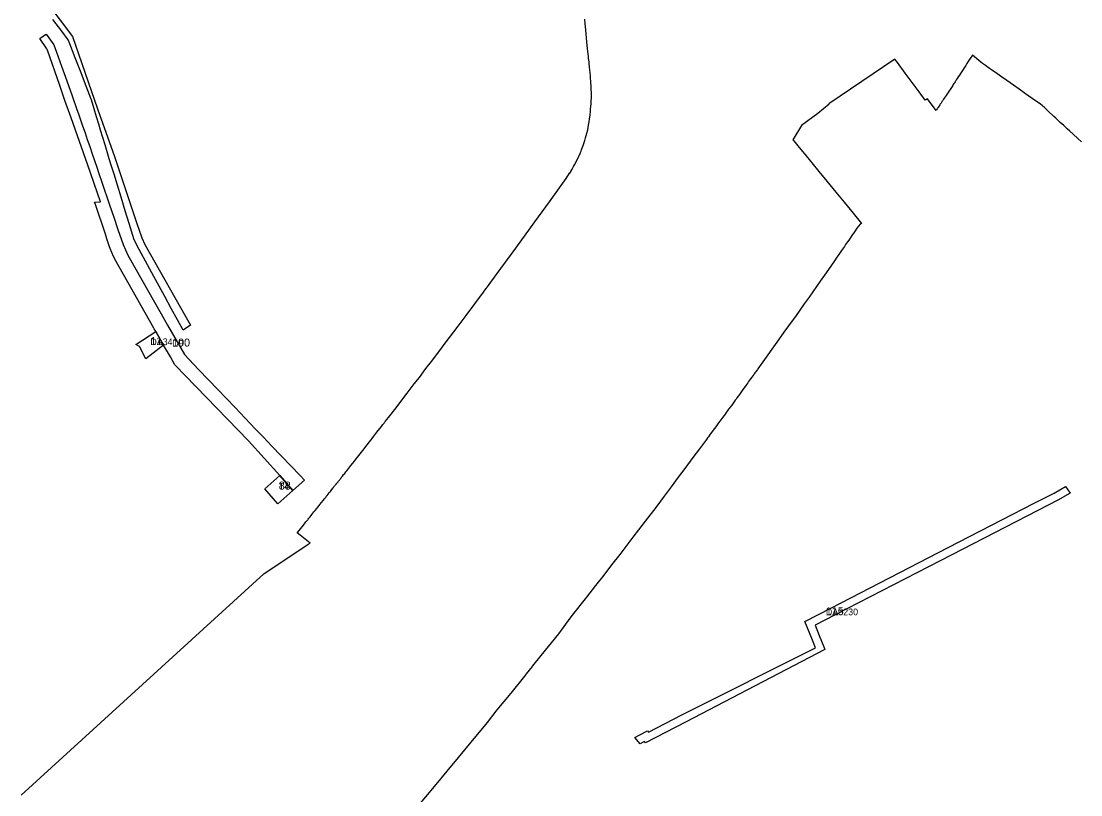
# Model space of a CAD drawing. Extents: x -537012 to -534603, y -1176562 to -1172739.
# Drawn here: x -536874 to -536080, y -1175140 to -1174561 of the extents above; entities that cross this region are included whole.
import ezdxf

# ---------------------------------------------------------------- set-up
doc = ezdxf.new("R2010")
doc.units = 0
for name, color, linetype in [('96120023', 7, 'Continuous'), ('96140023', 7, 'Continuous'), ('ID_VPO', 7, 'Continuous'), ('ID_VPS', 7, 'Continuous')]:
    doc.layers.add(name, color=color, linetype=linetype)

msp = doc.modelspace()

# ---------------------------------------------------------------- linework, layer by layer
at = {"layer": '96120023'}
for points in [[(-536873.93, -1175140.73), (-536692.18, -1174974.82), (-536658.72, -1174952.6), (-536657.33, -1174951.7), (-536664.85, -1174945.87), (-536667.13, -1174944.05), (-536663.21, -1174939.22), (-536661.92, -1174937.56), (-536661.13, -1174936.6), (-536660.5, -1174935.81), (-536660.09, -1174935.3), (-536659.66, -1174934.77), (-536659.18, -1174934.18), (-536658.84, -1174933.75), (-536658.33, -1174933.11), (-536657.79, -1174932.45), (-536657.46, -1174932.04), (-536656.02, -1174930.25), (-536654.54, -1174928.39), (-536653.63, -1174927.29), (-536652.46, -1174925.78), (-536651.59, -1174924.68), (-536650.69, -1174923.6), (-536649.1, -1174921.6), (-536647.46, -1174919.54), (-536647.36, -1174919.42), (-536646.89, -1174918.83), (-536646.5, -1174918.35), (-536646.16, -1174917.92), (-536645.95, -1174917.66), (-536645.77, -1174917.42), (-536645.6, -1174917.21), (-536645.28, -1174916.82), (-536645.18, -1174916.69), (-536645.08, -1174916.56), (-536645, -1174916.46), (-536644.93, -1174916.38), (-536644.87, -1174916.3), (-536644.8, -1174916.21), (-536644.72, -1174916.11), (-536644.65, -1174916.03), (-536644.56, -1174915.91), (-536644.47, -1174915.8), (-536644.39, -1174915.7), (-536644.3, -1174915.59), (-536644.25, -1174915.52), (-536644.21, -1174915.47), (-536644.15, -1174915.4), (-536644.09, -1174915.33), (-536644.07, -1174915.29), (-536642.86, -1174913.78), (-536642.19, -1174912.94), (-536641.63, -1174912.24), (-536641.59, -1174912.18), (-536640.3, -1174910.57), (-536639.98, -1174910.16), (-536639.78, -1174909.91), (-536639.26, -1174909.25), (-536638.99, -1174908.91), (-536638.53, -1174908.33), (-536638.16, -1174907.86), (-536637.78, -1174907.39), (-536637.74, -1174907.34), (-536637.68, -1174907.27), (-536637.64, -1174907.22), (-536637.61, -1174907.17), (-536637.58, -1174907.13), (-536637.54, -1174907.09), (-536637.46, -1174906.99), (-536637.44, -1174906.96), (-536637.41, -1174906.92), (-536637.38, -1174906.89), (-536637.36, -1174906.86), (-536637.33, -1174906.82), (-536637.3, -1174906.79), (-536637.28, -1174906.75), (-536637.26, -1174906.73), (-536637.16, -1174906.61), (-536637.08, -1174906.5), (-536636.98, -1174906.38), (-536636.87, -1174906.25), (-536636.61, -1174905.91), (-536636.43, -1174905.68), (-536636.22, -1174905.42), (-536636.05, -1174905.2), (-536635.67, -1174904.73), (-536635.46, -1174904.47), (-536635.19, -1174904.12), (-536634.89, -1174903.74), (-536634.7, -1174903.51), (-536634.45, -1174903.19), (-536634.25, -1174902.94), (-536633.94, -1174902.54), (-536633.76, -1174902.32), (-536633.61, -1174902.14), (-536633.5, -1174901.99), (-536633.36, -1174901.81), (-536633.19, -1174901.6), (-536632.24, -1174900.39), (-536631.48, -1174899.43), (-536630.64, -1174898.39), (-536629.96, -1174897.51), (-536626.77, -1174893.47), (-536625.41, -1174891.77), (-536624.22, -1174890.21), (-536622.94, -1174888.63), (-536621.83, -1174887.2), (-536620.94, -1174886.06), (-536617.99, -1174882.2), (-536614.51, -1174877.99), (-536612.89, -1174875.89), (-536610.91, -1174873.26), (-536609.59, -1174871.58), (-536608.06, -1174869.62), (-536606.38, -1174867.43), (-536604.86, -1174865.53), (-536603.85, -1174864.22), (-536602.78, -1174862.8), (-536602.25, -1174862.13), (-536601.9, -1174861.7), (-536601.62, -1174861.35), (-536601.37, -1174861.02), (-536601.09, -1174860.66), (-536598.59, -1174857.48), (-536593, -1174850.36), (-536588.63, -1174844.54), (-536584.67, -1174839.44), (-536579.41, -1174832.4), (-536575.45, -1174827.55), (-536570.59, -1174820.91), (-536566.46, -1174815.57), (-536560.15, -1174807.24), (-536556.11, -1174801.9), (-536546.4, -1174789.03), (-536540.49, -1174781.02), (-536527.39, -1174763.63), (-536525.68, -1174761.21), (-536525.56, -1174761.05), (-536525.44, -1174760.88), (-536525.37, -1174760.79), (-536525.32, -1174760.72), (-536525.29, -1174760.69), (-536525.22, -1174760.59), (-536525.2, -1174760.56), (-536525.17, -1174760.53), (-536525.14, -1174760.49), (-536525.12, -1174760.45), (-536525.1, -1174760.43), (-536525.09, -1174760.41), (-536525.06, -1174760.38), (-536525.03, -1174760.34), (-536524.99, -1174760.27), (-536524.96, -1174760.24), (-536524.95, -1174760.23), (-536524.93, -1174760.2), (-536524.9, -1174760.17), (-536524.89, -1174760.15), (-536524.88, -1174760.14), (-536524.87, -1174760.12), (-536524.87, -1174760.11), (-536524.86, -1174760.11), (-536524.86, -1174760.1), (-536524.85, -1174760.09), (-536524.84, -1174760.08), (-536524.83, -1174760.07), (-536524.83, -1174760.06), (-536524.82, -1174760.06), (-536524.82, -1174760.05), (-536524.81, -1174760.04), (-536524.78, -1174760), (-536524.74, -1174759.94), (-536524.56, -1174759.7), (-536524.44, -1174759.54), (-536523.15, -1174757.8), (-536521.87, -1174756.07), (-536514.37, -1174745.87), (-536503.23, -1174730.7), (-536489.05, -1174710.98), (-536478.01, -1174695.81), (-536471.74, -1174687.11), (-536465.57, -1174678.46), (-536464.62, -1174677.1), (-536464.52, -1174676.95), (-536464.35, -1174676.7), (-536463.75, -1174675.8), (-536463.63, -1174675.62), (-536463.59, -1174675.57), (-536463.51, -1174675.44), (-536463.5, -1174675.42), (-536463.47, -1174675.39), (-536463.37, -1174675.23), (-536462.9, -1174674.51), (-536462.79, -1174674.34), (-536461.84, -1174672.83), (-536461.7, -1174672.59), (-536461.07, -1174671.55), (-536459.91, -1174669.56), (-536459.2, -1174668.27), (-536457.41, -1174664.84), (-536455.91, -1174661.68), (-536455.65, -1174661.05), (-536455.33, -1174660.34), (-536455.01, -1174659.61), (-536454.7, -1174658.86), (-536454.33, -1174657.95), (-536454.16, -1174657.54), (-536453.91, -1174656.9), (-536453.67, -1174656.3), (-536452.72, -1174653.7), (-536452.21, -1174652.22), (-536451.93, -1174651.39), (-536451.52, -1174650.08), (-536450.88, -1174647.95), (-536449.92, -1174644.38), (-536449.34, -1174641.85), (-536448.99, -1174640.13), (-536448.64, -1174638.38), (-536448.26, -1174636.09), (-536447.97, -1174634.02), (-536447.54, -1174630.65), (-536447.32, -1174628.16), (-536447.22, -1174626.58), (-536447.15, -1174625.52), (-536447.07, -1174624.96), (-536447.04, -1174624.72), (-536446.99, -1174624.33), (-536446.98, -1174624.28), (-536446.98, -1174624.26), (-536446.98, -1174624.21), (-536446.97, -1174624.17), (-536446.97, -1174624.14), (-536446.96, -1174624.12), (-536446.96, -1174624.11), (-536446.96, -1174624.08), (-536446.96, -1174624.07), (-536446.96, -1174624.06), (-536446.96, -1174624.05), (-536446.95, -1174624.04), (-536446.95, -1174624.03), (-536446.95, -1174624.02), (-536446.95, -1174624.01), (-536446.95, -1174624), (-536446.95, -1174623.99), (-536446.95, -1174623.98), (-536446.94, -1174623.94), (-536446.94, -1174623.91), (-536446.93, -1174623.79), (-536446.92, -1174623.71), (-536446.85, -1174623.08), (-536446.83, -1174622.89), (-536446.81, -1174622.59), (-536446.78, -1174622.29), (-536446.77, -1174622.08), (-536446.75, -1174621.87), (-536446.74, -1174621.65), (-536446.71, -1174621.32), (-536446.69, -1174620.98), (-536446.67, -1174620.5), (-536446.65, -1174620.02), (-536446.63, -1174619.64), (-536446.62, -1174619.25), (-536446.6, -1174618.72), (-536446.6, -1174618.45), (-536446.59, -1174618.18), (-536446.58, -1174617.76), (-536446.58, -1174617.47), (-536446.57, -1174615.98), (-536446.59, -1174614.72), (-536446.61, -1174613.55), (-536446.65, -1174612.34), (-536446.69, -1174611.08), (-536446.75, -1174609.77), (-536446.83, -1174608.4), (-536446.9, -1174607.24), (-536447.01, -1174605.57), (-536447.17, -1174603.39), (-536447.34, -1174601.34), (-536447.53, -1174599.2), (-536447.71, -1174597.24), (-536447.96, -1174594.69), (-536448.17, -1174592.58), (-536448.34, -1174590.95), (-536448.61, -1174588.44), (-536448.76, -1174587.01), (-536448.98, -1174584.97), (-536449.37, -1174581.34), (-536449.94, -1174575.9), (-536450.52, -1174570.12), (-536450.82, -1174566.91), (-536451.2, -1174562.49), (-536451.47, -1174559.05)], [(-536079.3, -1174650.88), (-536082.01, -1174648.5), (-536085.41, -1174645.3), (-536088.04, -1174642.95), (-536089.94, -1174641.13), (-536092.56, -1174638.79), (-536095.25, -1174636.35), (-536098.56, -1174633.22), (-536099.93, -1174631.93), (-536100.95, -1174630.96), (-536103.19, -1174628.87), (-536104.24, -1174627.86), (-536105.3, -1174626.86), (-536106.35, -1174625.83), (-536107.18, -1174625.1), (-536107.87, -1174624.42), (-536108.61, -1174623.75), (-536110.05, -1174622.73), (-536111.04, -1174622.04), (-536112.12, -1174621.27), (-536116.14, -1174618.45), (-536121.16, -1174614.93), (-536125.9, -1174611.57), (-536130.17, -1174608.6), (-536135.2, -1174605.08), (-536137.66, -1174603.31), (-536138.82, -1174602.51), (-536140.95, -1174601), (-536142.93, -1174599.59), (-536144.22, -1174598.71), (-536146.68, -1174596.96), (-536148.12, -1174595.95), (-536151.14, -1174593.83), (-536153.43, -1174592.24), (-536154.69, -1174591.35), (-536161.02, -1174586), (-536162.61, -1174588.43), (-536163.84, -1174590.35), (-536165.06, -1174592.19), (-536165.99, -1174593.67), (-536167.18, -1174595.51), (-536168.01, -1174596.73), (-536168.51, -1174597.52), (-536168.91, -1174598.14), (-536169.51, -1174599.07), (-536169.96, -1174599.75), (-536170.74, -1174600.94), (-536171.61, -1174602.29), (-536172.46, -1174603.58), (-536173.08, -1174604.53), (-536174.02, -1174605.97), (-536174.53, -1174606.75), (-536174.89, -1174607.3), (-536175.32, -1174607.98), (-536175.77, -1174608.64), (-536177.24, -1174610.91), (-536177.76, -1174611.69), (-536178.42, -1174612.69), (-536179.23, -1174613.94), (-536179.9, -1174614.97), (-536180.7, -1174616.18), (-536181.41, -1174617.25), (-536182.04, -1174618.24), (-536182.54, -1174618.98), (-536183.18, -1174619.95), (-536183.59, -1174620.56), (-536183.9, -1174621.04), (-536184.15, -1174621.43), (-536184.47, -1174621.9), (-536184.7, -1174622.26), (-536184.9, -1174622.57), (-536185.09, -1174622.85), (-536185.3, -1174623.16), (-536186.67, -1174625.25), (-536187.05, -1174625.84), (-536187.29, -1174626.2), (-536187.87, -1174627.06), (-536188.1, -1174627.42), (-536189.64, -1174625.36), (-536194.63, -1174618.67), (-536195.88, -1174619.5), (-536196.3, -1174619.77), (-536200.96, -1174613.49), (-536206.13, -1174606.52), (-536211.43, -1174599.38), (-536217.25, -1174591.53), (-536219.04, -1174589.12), (-536268.55, -1174622.53), (-536268.37, -1174622.75), (-536276.88, -1174629.61), (-536289.09, -1174638.79), (-536295.57, -1174649.55), (-536294.94, -1174650.3), (-536291.94, -1174653.91), (-536288.31, -1174658.27), (-536286.67, -1174660.24), (-536276.09, -1174673.15), (-536270.11, -1174680.44), (-536263.42, -1174688.6), (-536257.18, -1174696.21), (-536250.45, -1174704.41), (-536244.02, -1174712.25), (-536245.11, -1174712.76), (-536247.51, -1174715.63), (-536249.49, -1174718.5), (-536251.29, -1174721.15), (-536252.65, -1174723.1), (-536253.72, -1174724.65), (-536254.55, -1174725.87), (-536255.36, -1174727), (-536256.05, -1174728.03), (-536256.98, -1174729.37), (-536259.12, -1174732.46), (-536261.08, -1174735.31), (-536262.62, -1174737.5), (-536264.46, -1174740.15), (-536268.95, -1174746.62), (-536271.83, -1174750.79), (-536275.22, -1174755.48), (-536283.4, -1174767.33), (-536286.98, -1174772.33), (-536293.67, -1174781.82), (-536295.37, -1174784.2), (-536302.21, -1174793.69), (-536306.21, -1174799.45), (-536319.22, -1174817.54), (-536321.7, -1174821.05), (-536322.11, -1174821.6), (-536322.8, -1174822.56), (-536323.37, -1174823.37), (-536323.96, -1174824.17), (-536324.46, -1174824.88), (-536324.93, -1174825.53), (-536325.38, -1174826.13), (-536326.49, -1174827.68), (-536327.04, -1174828.44), (-536327.95, -1174829.68), (-536328.7, -1174830.71), (-536329.35, -1174831.62), (-536330.14, -1174832.7), (-536330.7, -1174833.51), (-536333.49, -1174837.29), (-536335.68, -1174840.44), (-536336.55, -1174841.54), (-536337.44, -1174842.77), (-536338.16, -1174843.75), (-536338.79, -1174844.63), (-536341.42, -1174848.25), (-536342.53, -1174849.75), (-536343.34, -1174850.86), (-536343.77, -1174851.45), (-536344.78, -1174852.84), (-536345.53, -1174853.83), (-536346.36, -1174854.99), (-536347.15, -1174856.04), (-536347.98, -1174857.21), (-536349.51, -1174859.28), (-536350.3, -1174860.39), (-536351.21, -1174861.58), (-536353.3, -1174864.49), (-536355.24, -1174867), (-536356.53, -1174868.82), (-536357.54, -1174870.19), (-536358.05, -1174870.93), (-536358.91, -1174872.07), (-536359.54, -1174872.92), (-536360.38, -1174874.04), (-536365.51, -1174880.99), (-536370.44, -1174887.54), (-536376.43, -1174895.8), (-536381.45, -1174902.35), (-536386.87, -1174909.63), (-536391.96, -1174916.59), (-536398.28, -1174925), (-536406.2, -1174935.2), (-536411.22, -1174941.83), (-536415.59, -1174947.33), (-536425.14, -1174960.28), (-536431.45, -1174968.05), (-536437.27, -1174975.81), (-536443.42, -1174983.42), (-536450.22, -1174992.32), (-536461.87, -1175006.88), (-536471.26, -1175019.83), (-536484.52, -1175036.01), (-536490.68, -1175043.69), (-536491.08, -1175044.18), (-536495.33, -1175049.61), (-536495.34, -1175049.61), (-536495.77, -1175050.17), (-536507.02, -1175064.09), (-536517.37, -1175076.71), (-536524.65, -1175086.09), (-536536.95, -1175100.98), (-536546.34, -1175112.47), (-536555, -1175122.74), (-536563.09, -1175132.53), (-536578.54, -1175151.06)]]:
    msp.add_lwpolyline(points, dxfattribs=at)
for points in [[(-536858.6, -1174572.62), (-536855.32, -1174570.31), (-536853.23, -1174573.07), (-536849.37, -1174578.18), (-536847.43, -1174583.64), (-536843.67, -1174594.24), (-536839.8, -1174605.15), (-536835.8, -1174616.43), (-536832.15, -1174626.71), (-536830.96, -1174630.05), (-536829.94, -1174633.05), (-536827.9, -1174639.03), (-536826.1, -1174644.29), (-536824.45, -1174649.13), (-536822.6, -1174654.56), (-536820.76, -1174659.94), (-536817.34, -1174669.94), (-536815.69, -1174674.78), (-536813.53, -1174681.1), (-536807.68, -1174698.23), (-536804.55, -1174707.41), (-536801.4, -1174716.65), (-536797.54, -1174727.95), (-536794.07, -1174735.98), (-536783.59, -1174754.35), (-536774.06, -1174771.04), (-536769, -1174779.9), (-536764.23, -1174788.25), (-536754.29, -1174805.66), (-536751.55, -1174810.45), (-536740.95, -1174821.53), (-536733.51, -1174829.3), (-536726.48, -1174836.66), (-536720.34, -1174843.08), (-536713.63, -1174850.1), (-536698.47, -1174865.96), (-536692.66, -1174872.04), (-536689.34, -1174875.51), (-536685.97, -1174879.04), (-536671.86, -1174893.79), (-536664.96, -1174901.01), (-536661.56, -1174904.56), (-536670.24, -1174912.25), (-536680.18, -1174901.02), (-536703.62, -1174875.13), (-536758.86, -1174818.06), (-536762.07, -1174812.08), (-536767.18, -1174803.45), (-536773.05, -1174793.18), (-536774.18, -1174791.2), (-536774.51, -1174790.62), (-536803.79, -1174738.89), (-536805.19, -1174735.68), (-536805.44, -1174735.08), (-536807.71, -1174729.63), (-536809.68, -1174723.6), (-536810.85, -1174720.21), (-536818.3, -1174697.92), (-536818.87, -1174696.2), (-536814.54, -1174695.99), (-536824.01, -1174668.43), (-536836.56, -1174633.08), (-536841.1, -1174619.95), (-536844.98, -1174608.71), (-536854.16, -1174582.13), (-536854.6, -1174581.18), (-536859.98, -1174573.6)], [(-536680.18, -1174901.02), (-536670.24, -1174912.25), (-536681.47, -1174922.19), (-536691.41, -1174910.96)]]:
    msp.add_lwpolyline(points, close=True, dxfattribs=at)
at = {"layer": '96140023'}
msp.add_lwpolyline([(-536872.53, -1174522.68), (-536835.56, -1174572.01), (-536816.72, -1174626.2), (-536804.01, -1174662.07), (-536786.98, -1174712.81), (-536785.77, -1174716.37), (-536783.63, -1174722.98), (-536781.34, -1174727.87), (-536747.07, -1174788.38), (-536752.61, -1174792.19), (-536756.9, -1174784.28), (-536761.47, -1174775.86), (-536766.33, -1174766.9), (-536775.98, -1174749.09), (-536785.46, -1174731.59), (-536789.29, -1174724.52), (-536793.09, -1174712.05), (-536795.95, -1174702.67), (-536799.06, -1174692.48), (-536801.82, -1174683.44), (-536804.3, -1174675.31), (-536806.4, -1174668.42), (-536807.87, -1174663.59), (-536811.05, -1174653.16), (-536812.72, -1174647.7), (-536814.38, -1174642.24), (-536815.78, -1174637.65), (-536817.43, -1174632.24), (-536819.28, -1174626.16), (-536821.35, -1174619.37), (-536821.47, -1174619.05), (-536825.27, -1174609.19), (-536829.53, -1174598.09), (-536833.4, -1174588), (-536837.45, -1174577.47), (-536838.62, -1174574.44), (-536843.46, -1174568.06), (-536850.22, -1174559.15)], dxfattribs=at)
for points in [[(-536780.57, -1174813.49), (-536785.27, -1174804.29), (-536788.03, -1174802.83), (-536773.05, -1174793.18), (-536767.18, -1174803.45)], [(-536271.65, -1175031.44), (-536376.08, -1175085.82), (-536406.02, -1175101.41), (-536406.67, -1175100.37), (-536407.88, -1175101.01), (-536410.03, -1175102.14), (-536413.98, -1175097.44), (-536410.68, -1175095.7), (-536404.54, -1175092.46), (-536403.87, -1175093.53), (-536378.81, -1175080.48), (-536278.61, -1175030.21), (-536281.47, -1175023.11), (-536286.55, -1175010.49), (-536266.52, -1175000.17), (-536179.07, -1174955.11), (-536138.87, -1174934.4), (-536114.61, -1174921.9), (-536099.73, -1174914.23), (-536091.18, -1174909.41), (-536087.7, -1174914.34), (-536096.88, -1174919.51), (-536111.86, -1174927.23), (-536136.12, -1174939.73), (-536176.32, -1174960.44), (-536263.77, -1175005.5), (-536278.94, -1175013.32), (-536275.9, -1175020.87), (-536272.46, -1175029.43)]]:
    msp.add_lwpolyline(points, close=True, dxfattribs=at)

# ---------------------------------------------------------------- texts
at = {"layer": '96120023'}
for s, rotation, p in [('D9', 360, (-536760.77, -1174804.41)), ('T4', 0, (-536680.82, -1174911.61))]:
    msp.add_text(s, height=5, rotation=rotation, dxfattribs=at).set_placement(p)
at = {"layer": '96140023'}
for s, rotation, p in [('DA34', 360, (-536777.16, -1174803.33)), ('DA3230', 0, (-536270.85, -1175005.78))]:
    msp.add_text(s, height=5, rotation=rotation, dxfattribs=at).set_placement(p)
at = {"layer": 'ID_VPO'}
for s, p in [('11', (-536777.16, -1174803.33)), ('115', (-536270.85, -1175005.78))]:
    msp.add_text(s, height=6, rotation=360, dxfattribs=at).set_placement(p)
at = {"layer": 'ID_VPS'}
for s, rotation, p in [('100', 360, (-536760.77, -1174804.41)), ('88', 0, (-536680.82, -1174911.61))]:
    msp.add_text(s, height=6, rotation=rotation, dxfattribs=at).set_placement(p)

doc.saveas('drawing.dxf')
